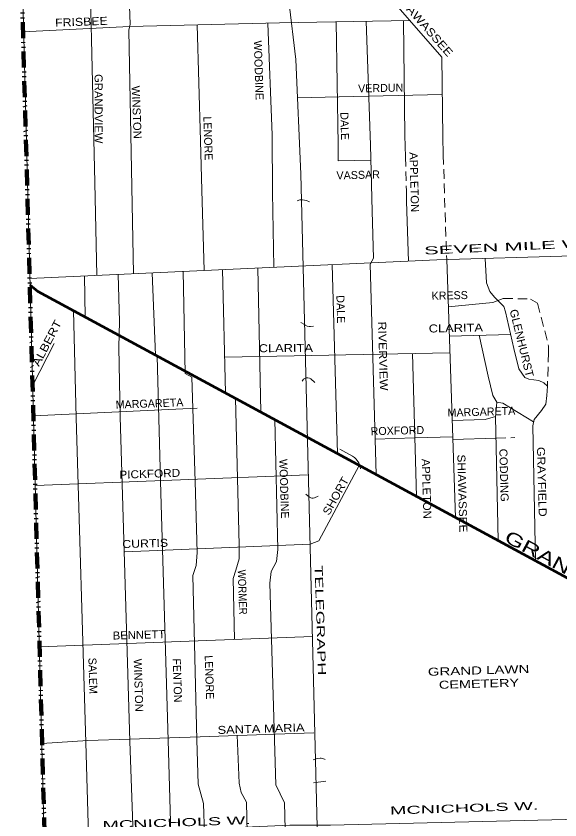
# Model space of a CAD drawing. Extents: x 34705 to 138605, y 34275 to 143551.
# Drawn here: x 34923 to 40021, y 130370 to 137900 of the extents above; entities that cross this region are included whole.
import ezdxf
from ezdxf.enums import TextEntityAlignment as Align

# ---------------------------------------------------------------- set-up
doc = ezdxf.new("R2010")
doc.units = 0
doc.header["$LTSCALE"] = 30
doc.linetypes.add('DASH_DOUBLE_DOT', pattern=[9.2, 5, -1.2, 0.3, -1.2, 0.3, -1.2])
doc.linetypes.add('MEDIUM_DASHED', pattern=[4.5, 3, -1.5])
for name, color, linetype, lineweight in [('1', 7, 'Continuous', 13), ('11', 7, 'Continuous', 13), ('59', 7, 'DASH_DOUBLE_DOT', 106)]:
    doc.layers.add(name, color=color, linetype=linetype, lineweight=lineweight)

msp = doc.modelspace()

# ---------------------------------------------------------------- linework, layer by layer
at = {"layer": '1'}
for p, q in [((34922.9, 140631.57), (35253.71, 127582.24)), ((38959.65, 135620.43), (39040.93, 133203.55)), ((37885.33, 135572.6), (37936.47, 133801.44)), ((38983.78, 134902.98), (39559.29, 134916.68)), ((35079.84, 134441.13), (35278.98, 134832.68)), ((35079.84, 134441.13), (35278.98, 134832.68)), ((36880.01, 134704.44), (38989.1, 134744.79)), ((38638.33, 134738.08), (38676.16, 133401.01)), ((35087.08, 134155.4), (36619.68, 134227.87)), ((39420.33, 133946.16), (39424.96, 133946.31)), ((35103.59, 133504.07), (37662.4, 133604.04)), ((35942.16, 132881.96), (37678.81, 132952.01)), ((35141.94, 131991.45), (37702.68, 132087.32))]:
    msp.add_line(p, q, dxfattribs=at)
at = {"layer": '1', "linetype": 'MEDIUM_DASHED'}
for p, q in [((38926.71, 136600.25), (38959.65, 135620.43)), ((38573.01, 136580.25), (38581.45, 136262.67)), ((39424.96, 133946.31), (39596.72, 133951.81)), ((39597, 133951.81), (39597.87, 133951.84))]:
    msp.add_line(p, q, dxfattribs=at)
at = {"layer": '1'}
for points in [[(37454.38, 140703.77), (37375.53, 140338.99), (37375.53, 140279.38), (37330.84, 140078.2), (37271.25, 139541.72), (37293.59, 139079.75), (37397.87, 138438.96), (37479.81, 138044.05), (37546.85, 137492.67), (37591.54, 136419.71), (37811.41, 127682.75)], [(35620.57, 140651.47), (35612.55, 140391.92), (35577.76, 140338.8), (35596.07, 139366.17), (35599.73, 139162.4), (35607.06, 138790.57), (35617.53, 138219.19), (35661.99, 136341.15), (35680.04, 135470.94)], [(35925.4, 140265.26), (35943.98, 139292.9), (35949.47, 139083.64), (35954.96, 138821.71), (35960.46, 138667.84), (35991.59, 137823.44), (35978.77, 137768.49), (36022.55, 135486.73)], [(38287.12, 138235.79), (38914.16, 137514.46), (38922.24, 136769.3), (38926.71, 136600.25)], [(34987.85, 137752.06), (35984.66, 137801.36), (37391.64, 137836.26), (38613.89, 137859.88)], [(36619.78, 137817.11), (36650.78, 136729.92), (36663.6, 136267.88), (36687.27, 135517.37)], [(37284.28, 137831.53), (37323.65, 136786.9), (37327.58, 136248.07), (37338.62, 135548.4)], [(37922.01, 137846.51), (37942.3, 136698.36), (37942.25, 136543.8), (38249.05, 136550.78)], [(38204.55, 137851.97), (38245.31, 136691.91), (38261.79, 136071.32), (38274.58, 135631.16), (38243.23, 135574.71), (38298.6, 133605.4)], [(38553.92, 137858.72), (38567.65, 136782.19), (38573.01, 136580.25)], [(37561.82, 137133.34), (37950.22, 137142.93), (38917.93, 137166.77)], [(35050.01, 135441.89), (38867.68, 135617.88), (40146.22, 135653.27), (40348.36, 135643.16), (42072.86, 135638.1), (42926.9, 135633.05), (44579.39, 135678.54), (51671.96, 135890.86), (53501.32, 135931.3), (56282, 136022.29), (57388.72, 136042.52), (58020.4, 136042.52), (61877.48, 136194.17), (62342.4, 136219.45), (65279.74, 136335.71), (66593.65, 136340.77), (68808.33, 136381.21), (71284.55, 136401.43), (76864.35, 136528)], [(38581.45, 136262.67), (38584.14, 136161.61), (38601.54, 135605.61)], [(37558.97, 136170.27), (37582.32, 136177.95), (37608.21, 136179.84), (37643.84, 136173.08), (37673.65, 136161.49)], [(39320.88, 135630.43), (39332.29, 135402.13), (39364.95, 135320.45), (39408.5, 135265.99), (39495.61, 135178.86), (39511.94, 135129.85), (39588.15, 134786.76), (39637.15, 134596.16), (39691.59, 134514.47), (39729.7, 134498.14), (39822.25, 134487.24), (39871.24, 134465.46), (39903.91, 134432.79), (39898.46, 134345.65), (39887.57, 134263.97), (39849.47, 134204.06), (39778.69, 134122.38), (39767.81, 134062.47), (39791.79, 132797.08)], [(37189.87, 135540.54), (37218.37, 134190.17), (37347.71, 134120.16), (37377.91, 132902.64), (37365.37, 132789.74), (37315.21, 132695.65), (37302.67, 132589.02), (37359.1, 130699.45), (37440.61, 130530.1), (37511.01, 127671.07)], [(35564.96, 135465.63), (35570.87, 135082.21), (35461.47, 135140.95), (35486.2, 134138.09), (35575.93, 131095.66), (35603.39, 130225.61), (35619.87, 129182.93), (35652.83, 127905.78), (35662.29, 127598.32)], [(35878.83, 135480.1), (35892.71, 135038.36), (35885.38, 134798.41), (35898.2, 134147.25), (35987.92, 131106.65), (36019.05, 130229.27), (36033.7, 129171.94), (36066.59, 127974.42)], [(36198.03, 135494.82), (36230.63, 134724.12), (36245.49, 134715.44), (36280.9, 133431.06), (36348.65, 131115.81), (36372.45, 130242.1), (36394.43, 129190.25), (36427.39, 127958.9), (36439, 127628.88)], [(36490.17, 135510.11), (36506.88, 134551.8), (36569.73, 134518.26), (36600.45, 133540.44), (36620.6, 132875.53), (36611.44, 132752.81), (36580.31, 132659.39), (36618.77, 131119.41), (36629.75, 130705.44), (36679.19, 130524.11), (36690.18, 130237.91), (36713.98, 129298.25), (36743.28, 128010.12), (36754.84, 127642.86)], [(36856.69, 135525.18), (36885.67, 134370.28), (36980.96, 134318.69), (37014.23, 132946.55), (37014.23, 132814.83), (36982.87, 132708.2), (36957.79, 132632.93), (36970.22, 132061.18)], [(38973.29, 135177.33), (39392.17, 135216.98), (39490.16, 135255.1)], [(37591.57, 135028.31), (37625.63, 135009.74), (37633.49, 135004.34), (37650.46, 134996.43), (37668.78, 134992.5), (37681.9, 134992.19), (37710.27, 134995.56)], [(39265.34, 134909.68), (39346.82, 134527.21), (39390.72, 134345.31), (39428.34, 134282.58), (39422.07, 134207.32), (39415.8, 134144.59), (39442.27, 132986.29)], [(37604.95, 134478.6), (37610.28, 134488.36), (37617.61, 134497.27), (37635.73, 134508.07), (37646.6, 134510.82), (37657.83, 134511.3), (37672.45, 134508.25), (37685.67, 134501.29), (37724.64, 134466.65)], [(39428.34, 134282.58), (39484.66, 134274.06), (39773.21, 134099.36)], [(39010.39, 134111.65), (39319.2, 134119.64), (39416.33, 134149.93)], [(38289.24, 133938.27), (38659.08, 133949.83), (39015.48, 133958.69), (39016.28, 133933.22), (39420.33, 133946.16)], [(38152.59, 133659.69), (38146.68, 133688.93), (38134.54, 133716.19), (38109.79, 133749.65), (38093.76, 133765.42), (38075.09, 133777.92), (37956.59, 133843.63)], [(38139.85, 133691.34), (37761.12, 132983.77), (37678.76, 132953.81)], [(37640.04, 133420.84), (37673.06, 133393.68), (37684.84, 133387.39), (37693.99, 133384.86), (37706.64, 133384.13), (37719.35, 133386.59), (37753.89, 133402.26)], [(35164.89, 131085.93), (35595.13, 131114.62), (35984.66, 131126.25), (36647.45, 131149.52), (37350.94, 131172.78), (37714.68, 131184.33)], [(35164.89, 131085.93), (35595.13, 131114.62), (35984.66, 131126.25), (36647.45, 131149.52), (37350.94, 131172.78), (37714.68, 131184.33)], [(35186.55, 130231.58), (35458.2, 130231.58), (37489.31, 130321.29), (37869.15, 130321.29), (40074.35, 130374.07), (43172.44, 130363.51), (44385.83, 130374.07), (48329.33, 130516.55), (49305.31, 130558.77), (49933.11, 130564.05), (54929.09, 130685.43), (56976.03, 130759.31), (58131.38, 130785.7), (58991.3, 130812.08), (60184.9, 130901.8), (61393.02, 130975.68), (61503.8, 130980.96), (63404.33, 131007.34), (65002.84, 131017.9), (66400.87, 131039.01), (66997.01, 131039.01), (67635.36, 131075.95), (68722.14, 131123.45), (70126.76, 131153.79)], [(36995.41, 131165.19), (37014.23, 130713.57), (37033.04, 130625.75), (37083.2, 130537.94), (37146.23, 127656.72)], [(37708.12, 130933.06), (37746.7, 130944.82), (37773.22, 130949.23), (37783.99, 130949.39), (37798.29, 130946.77), (37820.68, 130935.13)], [(37827.49, 130734.47), (37755.18, 130722.26), (37712.27, 130718.38)]]:
    msp.add_lwpolyline(points, dxfattribs=at)
at = {"layer": '1', "lineweight": 53}
msp.add_lwpolyline([(35051.57, 135383.85), (35124.2, 135323.83), (40544.24, 132389.75), (44352.38, 130313.49), (48721.15, 127927.26), (52359.24, 125955.06), (53781.74, 125169.15), (55156.63, 124418.97), (56043.46, 123936.71), (56442.24, 123716.41), (57585, 123085.31), (70109.98, 116247.42), (80624.23, 110526.89), (82336.58, 109591.28)], dxfattribs=at)
at = {"layer": '1', "linetype": 'MEDIUM_DASHED'}
msp.add_lwpolyline([(39490.16, 135255.1), (39746.03, 135249.65), (39811.36, 135211.53), (39914.79, 134808.54), (39914.79, 134748.64), (39903.86, 134432.85)], dxfattribs=at)
at = {"layer": '59'}
msp.add_lwpolyline([(34926.08, 140631.66), (34977.99, 138118.71), (35197.94, 129943.33)], dxfattribs=at)

# ---------------------------------------------------------------- texts
at = {"layer": '11'}
for s, height, rotation, width, p in [('SHIAWASSEE', 75, 311.314, 1.2, (38706.16, 137811.68)), ('FRISBEE', 75, 2.205, 1.15, (35536.9, 137809.34)), ('GRANDVIEW', 75, 270, 1.05, (35658.89, 137031.96)), ('WINSTON', 75, 272.252, 1.05, (36016.06, 136997.38)), ('APPLETON', 75, 271.558, 1.05, (38618.14, 136343.38)), ('SEVEN MILE W.', 75, 2.633, 2.05, (39519.63, 135700.55)), ('GLENHURST', 75, 283.843, 1.05, (39626.53, 134828.08)), ('ALBERT', 75, 62.511, 1.2, (35245.72, 134819.52)), ('RIVERVIEW', 75, 271.56, 1.15, (38325.29, 134713.92)), ('CLARITA', 75, 1.19, 1.2, (39045.85, 134940.63)), ('CLARITA', 75, 0.42, 1.2, (37451.73, 134752.77)), ('CODDING', 75, 271.559, 1.05, (39459.4, 133597.62)), ('GRAYFIELD', 75, 271.558, 1.15, (39814, 133536.24)), ('APPLETON', 75, 271.558, 1.05, (38733.74, 133471.08)), ('SHIAWASSEE', 75, 271.56, 1.1, (39069, 133427.43)), ('PICKFORD', 75, 2.042, 1.1, (36177.52, 133575.33)), ('SHORT', 75, 60.729, 1.1, (37951.69, 133386.09)), ('GRAND RIVER', 120, 331.678, 1.45, (40200.59, 132599.88)), ('CURTIS', 75, 1.824, 1.15, (36134.27, 132922.69)), ('TELEGRAPH', 75, 271.84, 1.7, (37737.76, 132238.36)), ('WORMER', 75, 271.841, 0.9, (37007.67, 132502.48)), ('BENNETT', 75, 1.642, 1.05, (36075.53, 132066.46)), ('WINSTON', 75, 271.84, 1.05, (36033.27, 131629.97)), ('GRAND LAWN', 75, 1.665, 1.4, (39259.49, 131733.62)), ('CEMETERY', 75, 1.665, 1.35, (39263.12, 131608.68)), ('SANTA MARIA', 75, 1.717, 1.2, (37220.42, 131186.82)), ('MCNICHOLS W.', 75, 1.91, 1.85, (39124.13, 130443.22)), ('MCNICHOLS W.', 75, 1.91, 1.85, (36428.75, 130308.39))]:
    msp.add_text(s, height=height, rotation=rotation, dxfattribs=dict(at, width=width)).set_placement(p, align=Align.CENTER)
for s, rotation, p in [('WOODBINE', 271.832, (37160.12, 137391.43)), ('VERDUN', 1.3, (38341.51, 137188.74)), ('DALE', 271.559, (37966.19, 136867.95)), ('LENORE', 271.84, (36685.23, 136752.96)), ('VASSAR', 1.5, (38130.82, 136374.72)), ('KRESS', 1.272, (38988.46, 135246.01)), ('DALE', 271.559, (37929.15, 135152.95)), ('MARGARETA', 2.105, (36175.19, 134233.78)), ('MARGARETA', 1.823, (39285.88, 134155.75)), ('ROXFORD', 1.447, (38498.18, 133979.64)), ('WOODBINE', 271.84, (37398.65, 133470.85)), ('SALEM', 271.84, (35605.94, 131718.83)), ('FENTON', 271.84, (36397.77, 131675.55)), ('LENORE', 271.84, (36697.81, 131704.8))]:
    msp.add_text(s, height=75, rotation=rotation, dxfattribs=at).set_placement(p, align=Align.CENTER)

doc.saveas('drawing.dxf')
